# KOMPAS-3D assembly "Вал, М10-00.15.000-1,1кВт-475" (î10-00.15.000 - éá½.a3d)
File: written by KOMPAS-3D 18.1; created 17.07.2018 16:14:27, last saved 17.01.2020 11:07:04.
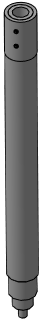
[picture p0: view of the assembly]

Document properties: Автор: Милов; Полное имя файла: D:\Magna\Магна Ins\Магна ins 10\М10-00.00.000\3Д\М10-00.15.000 - Вал.a3d

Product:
- Part/product: Вал  | designation М10-00.15.000-1,1кВт-475  | pos. 0
    Материал: Полипропилен  ГОСТ 26996-86 (density 900 kg/m3)
    Масса: 1.00808
    Раздел спецификации: Сборочные единицы
    Форматы листов документа: 2xA3
    Примечание: @100~)2xA3
  - Component [detail]: Вал  | designation М10-00.15.001-0,75кВт-1,1кВт-475  | pos. 3  | Масса: 0.818332; Раздел спецификации: Детали; Форматы листов документа: A3; Плотность: 2000; source file: М10-00.15.001 - Вал.m3d
  - Component [detail]: Фиксатор  | designation М10-00.15.002  | pos. 83  | Масса: 0.168272; Раздел спецификации: Детали; Форматы листов документа: A4; source file: М10-00.15.002 - Фиксатор.cdw, М10-00.15.002 - Фиксатор.m3d
  - Component [detail]: Фиксатор  | designation М10-00.15.002  | Масса: 0.168272; Раздел спецификации: Детали; Форматы листов документа: A4; source file: М10-00.15.002 - Фиксатор.cdw, М10-00.15.002 - Фиксатор.m3d
- Part/product: Вал  | designation М10-00.15.000-1,1кВт-425  | pos. 0
    Материал: Полипропилен  ГОСТ 26996-86 (density 900 kg/m3)
    Масса: 0.906297
    Раздел спецификации: Сборочные единицы
    Форматы листов документа: 2xA3
    Примечание: @100~)2xA3
  - Component [detail]: Вал  | designation М10-00.15.001-0,75кВт-1,1кВт-425  | pos. 3  | Масса: 0.716544; Раздел спецификации: Детали; Форматы листов документа: A3; Плотность: 2000; source file: М10-00.15.001 - Вал.m3d
  - Component [detail]: Фиксатор  | designation М10-00.15.002  | pos. 83  | Масса: 0.168272; Раздел спецификации: Детали; Форматы листов документа: A4; source file: М10-00.15.002 - Фиксатор.cdw, М10-00.15.002 - Фиксатор.m3d
  - Component [detail]: Фиксатор  | designation М10-00.15.002  | Масса: 0.168272; Раздел спецификации: Детали; Форматы листов документа: A4; source file: М10-00.15.002 - Фиксатор.cdw, М10-00.15.002 - Фиксатор.m3d
- Part/product: Вал  | designation М10-00.15.000-1,1кВт-375  | pos. 0
    Материал: Полипропилен  ГОСТ 26996-86 (density 900 kg/m3)
    Масса: 0.865208
    Раздел спецификации: Сборочные единицы
    Форматы листов документа: 2xA3
    Примечание: @100~)2xA3
  - Component [standard]: Винт A.М5-6gx12 ГОСТ 8878-93  | pos. 4  | Масса: 0.00118; Раздел спецификации: Стандартные изделия; Рассекать на разрезах: no; additional columns: А.М5-6gx12; Сталь 12Х18Н10Т ГОСТ 5632-72; source file: C:\Program Files\ASCON\KOMPAS-3D v18\Libs\PartLib\DATA\VAULT\methods\kompas\3d\PLib_Screw_GOST_8878-84_900.m3d
  - Component [detail]: Вал  | designation М10-00.15.001-0,75кВт-1,1кВт-375  | pos. 3  | Масса: 0.614757; Раздел спецификации: Детали; Форматы листов документа: A3; Плотность: 2000; source file: М10-00.15.001 - Вал.m3d
  - Component [detail]: Фиксатор  | designation М10-00.15.002  | pos. 83  | Масса: 0.168272; Раздел спецификации: Детали; Форматы листов документа: A4; source file: М10-00.15.002 - Фиксатор.cdw, М10-00.15.002 - Фиксатор.m3d
  - Component [detail]: Фиксатор  | designation М10-00.15.002  | Масса: 0.168272; Раздел спецификации: Детали; Форматы листов документа: A4; source file: М10-00.15.002 - Фиксатор.cdw, М10-00.15.002 - Фиксатор.m3d
- Part/product: Вал  | designation М10-00.15.000-0,75кВт-475  | pos. 0
    Материал: Полипропилен  ГОСТ 26996-86 (density 900 kg/m3)
    Масса: 1.01058
    Раздел спецификации: Сборочные единицы
    Форматы листов документа: 2xA3
    Примечание: @100~)2xA3
  - Component [detail]: Фиксатор  | designation М10-00.15.002  | pos. 71  | Масса: 0.168272; Раздел спецификации: Детали; Форматы листов документа: A4; source file: М10-00.15.002 - Фиксатор.cdw, М10-00.15.002 - Фиксатор.m3d
  - Component [detail]: Фиксатор  | designation М10-00.15.002  | pos. 76  | Масса: 0.168272; Раздел спецификации: Детали; Форматы листов документа: A4; source file: М10-00.15.002 - Фиксатор.cdw, М10-00.15.002 - Фиксатор.m3d
  - Component [detail]: Вал  | designation М10-00.15.001-0,75кВт-1,1кВт-475  | pos. 3  | Масса: 0.818332; Раздел спецификации: Детали; Форматы листов документа: A3; Плотность: 2000; source file: М10-00.15.001 - Вал.m3d
- Part/product: Вал  | designation М10-00.15.000-0,75кВт-425  | pos. 0
    Материал: Полипропилен  ГОСТ 26996-86 (density 900 kg/m3)
    Масса: 0.908797
    Раздел спецификации: Сборочные единицы
    Форматы листов документа: 2xA3
    Примечание: @100~)2xA3
  - Component [detail]: Фиксатор  | designation М10-00.15.002  | pos. 71  | Масса: 0.168272; Раздел спецификации: Детали; Форматы листов документа: A4; source file: М10-00.15.002 - Фиксатор.cdw, М10-00.15.002 - Фиксатор.m3d
  - Component [detail]: Вал  | designation М10-00.15.001-0,75кВт-1,1кВт-425  | pos. 3  | Масса: 0.716544; Раздел спецификации: Детали; Форматы листов документа: A3; Плотность: 2000; source file: М10-00.15.001 - Вал.m3d
- Part/product: Вал  | designation М10-00.15.000-0,75кВт-375  | pos. 0
    Материал: Полипропилен  ГОСТ 26996-86 (density 900 kg/m3)
    Масса: 0.519317
    Раздел спецификации: Сборочные единицы
    Форматы листов документа: 2xA3
    Примечание: @100~)2xA3
  - Component [detail]: Фиксатор  | designation М10-00.15.002  | pos. 71  | Масса: 0.168272; Раздел спецификации: Детали; Форматы листов документа: A4; source file: М10-00.15.002 - Фиксатор.cdw, М10-00.15.002 - Фиксатор.m3d
  - Component [detail]: Фиксатор  | designation М10-00.15.002  | Масса: 0.168272; Раздел спецификации: Детали; Форматы листов документа: A4; source file: М10-00.15.002 - Фиксатор.cdw, М10-00.15.002 - Фиксатор.m3d
  - Component [detail]: Вал  | designation М10-00.15.001-0,75кВт-1,1кВт-375  | pos. 3  | Масса: 0.614757; Раздел спецификации: Детали; Форматы листов документа: A3; Плотность: 2000; source file: М10-00.15.001 - Вал.m3d
  - Component [standard]: Винт A.М6-6gx16 ГОСТ 8878-93  | pos. 4  | Масса: 0.00243; Раздел спецификации: Стандартные изделия; Рассекать на разрезах: no; additional columns: А.М6-6gx16; Сталь 12Х18Н10Т ГОСТ 5632-72; source file: C:\Program Files\ASCON\KOMPAS-3D v18\Libs\PartLib\DATA\VAULT\methods\kompas\3d\PLib_Screw_GOST_8878-84_900.m3d
- Part/product: Вал  | designation М10-00.15.000-0,55кВт-475  | pos. 0
    Материал: Полипропилен  ГОСТ 26996-86 (density 900 kg/m3)
    Масса: 0.642468
    Раздел спецификации: Сборочные единицы
    Форматы листов документа: 2xA3
    Примечание: @100~)2xA3
  - Component [detail]: Вал  | designation М10-00.15.001-0,55кВт-475  | pos. 3  | Масса: 0.518873; Раздел спецификации: Детали; Форматы листов документа: A3; Плотность: 2000; source file: М10-00.15.001 - Вал.m3d
- Part/product: Вал  | designation М10-00.15.000-0,55кВт-425  | pos. 0
    Материал: Полипропилен  ГОСТ 26996-86 (density 900 kg/m3)
    Масса: 0.580892
    Раздел спецификации: Сборочные единицы
    Форматы листов документа: 2xA3
    Примечание: @100~)2xA3
  - Component [detail]: Вал  | designation М10-00.15.001-0,55кВт-425  | pos. 3  | Масса: 0.457297; Раздел спецификации: Детали; Форматы листов документа: A3; Плотность: 2000
- Part/product: Вал  | designation М10-00.15.000-0,55кВт-375  | pos. 0
    Материал: Полипропилен  ГОСТ 26996-86 (density 900 kg/m3)
    Масса: 0.519317
    Раздел спецификации: Сборочные единицы
    Форматы листов документа: 2xA3
    Примечание: @100~)2xA3
  - Component [detail]: Вал  | designation М10-00.15.001-0,55кВт-375  | pos. 3  | Масса: 0.395722; Раздел спецификации: Детали; Форматы листов документа: A3; Плотность: 2000
- Part/product: Вал  | designation М10-00.15.000-1,1кВт  | pos. 0
    Материал: Полипропилен  ГОСТ 26996-86 (density 900 kg/m3)
    Масса: 0.804509
    Раздел спецификации: Сборочные единицы
    Форматы листов документа: 2xA3
    Примечание: @100~)2xA3
  - Component [detail]: Вал  | designation М10-00.15.001-0,75кВт-1,1кВт  | pos. 3  | Масса: 0.614757; Раздел спецификации: Детали; Форматы листов документа: A3; Плотность: 2000; source file: М10-00.15.001 - Вал.m3d
  - Component [detail]: Фиксатор  | designation М10-00.15.002  | pos. 83  | Масса: 0.168272; Раздел спецификации: Детали; Форматы листов документа: A4; source file: М10-00.15.002 - Фиксатор.cdw, М10-00.15.002 - Фиксатор.m3d
- Part/product: Вал  | designation М10-00.15.000-0,75кВт  | pos. 0
    Материал: Полипропилен  ГОСТ 26996-86 (density 900 kg/m3)
    Масса: 0.807009
    Раздел спецификации: Сборочные единицы
    Форматы листов документа: 2xA3
    Примечание: @100~)2xA3
  - Component [detail]: Фиксатор  | designation М10-00.15.002  | pos. 71  | Масса: 0.168272; Раздел спецификации: Детали; Форматы листов документа: A4; source file: М10-00.15.002 - Фиксатор.cdw, М10-00.15.002 - Фиксатор.m3d
  - Component [detail]: Вал  | designation М10-00.15.001-0,75кВт-1,1кВт  | pos. 3  | Масса: 0.614757; Раздел спецификации: Детали; Форматы листов документа: A3; Плотность: 2000; source file: М10-00.15.001 - Вал.m3d
- Part/product: Вал  | designation М10-00.15.000-0,55кВт  | pos. 0
    Материал: Полипропилен  ГОСТ 26996-86 (density 900 kg/m3)
    Масса: 0.519317
    Раздел спецификации: Сборочные единицы
    Форматы листов документа: 2xA3
    Примечание: @100~)2xA3
  - Component [detail]: Вал  | designation М10-00.15.001  | pos. 3  | Масса: 0.395722; Раздел спецификации: Детали; Форматы листов документа: A3; Плотность: 2000; source file: М10-00.15.001 - Вал.cdw, М10-00.15.001 - Вал.m3d
- Part/product: Вал  | designation М10-00.15.000  | pos. 0
    Материал: Полипропилен  ГОСТ 26996-86 (density 900 kg/m3)
    Масса: 0.519317
    Раздел спецификации: Сборочные единицы
    Форматы листов документа: 2xA3
    Примечание: @100~)2xA3
    source file: М10-00.15.000 - Вал.cdw
  - Component [standard]: Винт A.М10-6gx40.21.12Х18Н10Т ГОСТ 11074-93  | pos. 5  | Материал: Сталь 12Х18Н10Т ГОСТ 5632-72 (density 1000 kg/m3); Масса: 0.01912; Раздел спецификации: Стандартные изделия; additional columns: А.М10-6gx40.21.12Х18Н10Т; Сталь 12Х18Н10Т ГОСТ 5632-72; source file: C:\Program Files\ASCON\KOMPAS-3D v18\Libs\PartLib\DATA\VAULT\methods\kompas\3d\PLib_Screw_GOST_11074-84_900.m3d
  - Component [standard]: Винт A.М5-6gx12.21.12Х18Н10Т ГОСТ 8878-93  | qty 2  | pos. 4  | Материал: Сталь 12Х18Н10Т ГОСТ 5632-72 (density 1000 kg/m3); Масса: 0.00118; Раздел спецификации: Стандартные изделия; additional columns: А.М5-6gx12.21.12Х18Н10Т; Сталь 12Х18Н10Т ГОСТ 5632-72; source file: C:\Program Files\ASCON\KOMPAS-3D v18\Libs\PartLib\DATA\VAULT\methods\kompas\3d\PLib_Screw_GOST_8878-84_900.m3d
  - Component [detail]: Фиксатор  | designation М5-00.20.002  | pos. 2
      Материал: Труба 30х4-12Х18Н10Т ГОСТ 9940-81 (density 7900 kg/m3)
      Масса: 0.102115
      Раздел спецификации: Детали
      Примечание: Заим.
      Плотность: 7900
      source file: ..\..\..\Магна ins 5\М5-00.00.000 - Насос Магна ins 5-C-N\3Д модель\М5-00.20.002 - Фиксатор.m3d
  - Component [detail]: Вал  | designation М10-00.15.001  | pos. 3  | Масса: 0.395722; Раздел спецификации: Детали; Форматы листов документа: A3; Плотность: 2000; source file: М10-00.15.001 - Вал.cdw, М10-00.15.001 - Вал.m3d
  - Component: Вал  | designation М10-00.15.001-01  | pos. 6  | Раздел спецификации: Стандартные изделия
  - Component: Винт A.М6-6gx16.21.12Х18Н10Т ГОСТ 8878-93  | pos. 8  | Раздел спецификации: Стандартные изделия
  - Component: Фиксатор  | designation М10-00.15.002  | pos. 7  | Раздел спецификации: Стандартные изделия; Форматы листов документа: А4; source file: М10-00.15.002 - Фиксатор.cdw
  - Component: Вал  | designation М10-00.15.001-02  | pos. 9  | Раздел спецификации: Стандартные изделия
  - Component: Фиксатор  | designation М11-00.01.002  | pos. 10  | Раздел спецификации: Стандартные изделия; Форматы листов документа: А4; Примечание: Заим.
  - Component: Винт A.М6-6gx16.21.12Х18Н10Т ГОСТ 8878-93  | pos. 12  | Раздел спецификации: Стандартные изделия

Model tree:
1. Массив по сетке:1  (with: Операция вращения:1, Операция выдавливания:1, Отверстие:1)  (labels: Полипропилен  ГОСТ 26996-86)  (2 pattern instances)
     Шаг 1 = 20; Угол раствора = 90; Расстояние = -24
2. Массив по сетке:2  (with: Операция вращения:1, Операция выдавливания:1, Отверстие:1)  (labels: Полипропилен  ГОСТ 26996-86)  (2 pattern instances)
     Шаг 1 = 20; Угол раствора = 90; Расстояние = -24

Referenced files in D:\Magna\Магна Ins\Магна ins 10\М10-00.00.000\3Д\: М10-00.15.002 - Фиксатор.cdw, М10-00.15.001 - Вал.m3d, М10-00.15.001 - Вал.cdw, М10-00.15.002 - Фиксатор.m3d, М10-00.15.000 - Вал.cdw
Referenced files in D:\Magna\Магна Ins\Магна ins 5\М5-00.00.000 - Насос Магна ins 5-C-N\3Д модель\: М5-00.20.002 - Фиксатор.m3d
Referenced files in C:\Program Files\ASCON\KOMPAS-3D v18\Libs\PartLib\DATA\VAULT\methods\kompas\3d\: PLib_Screw_GOST_8878-84_900.m3d, PLib_Screw_GOST_11074-84_900.m3d
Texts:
  Body Specification ( left align )
  Body Specificaton ( centered )
  3D_Doc-graphic.lyt,1.000000-4294967295-298842308658
  3D_Doc-graphic.lyt,1.000000-4294967295-298491746024
  3D_Doc-graphic.lyt,1.000000-4294967295-297339638027
  3D_Doc-graphic.lyt,1.000000-4294967295-281262858143
  3D_Doc-graphic.lyt,1.000000-4294967295-280836307480
  3D_Doc-graphic.lyt,1.000000-4294967295-214566056024
  Крепежное изделие ГОСТ
  М10-00.15.001 - 0,75кВт
  М10-00.15.001 - 0,75кВт-1,1кВт
  М10-00.15.001 - 0,55кВт-425
  М10-00.15.001 - 0,55кВт-475
  М10-00.15.001 - 0,75кВт-375
  М10-00.15.001 - 0,75кВт-425
  М10-00.15.001 - 0,75кВт-475
  М10-00.15.001 - 0,75кВт-1,1кВт-425
  М10-00.15.001 - 0,75кВт-1,1кВт-475
  Габарит двигателя  71
  Габарит двигателя 63
  Габарит двигателя  80
  @100~)2xA3
  М10-00.15.002 Фиксатор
